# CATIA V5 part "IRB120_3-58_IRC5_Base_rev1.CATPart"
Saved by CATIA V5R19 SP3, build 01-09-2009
Part number: Link0
Revision: ANY
Definition: UNKNOWN
Nomenclature: Link0
Source: Unknown
Bounding box of the stored display mesh (mm): x -211.2 to 90, y -90.262 to 90.262, z 0 to 166.334
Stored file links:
  Z:\Projects\ABB_Robotics\ABB LIB\V5\V5PARTS\ABB\120\IRB120_3-58_IRC5_Base_rev1.CATPart
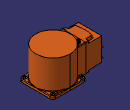
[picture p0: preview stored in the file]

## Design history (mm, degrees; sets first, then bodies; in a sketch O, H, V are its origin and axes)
Body1 "NONE" (main body)
  Solid1: solid without history
Body2 "NONE"
  Solid2: solid without history
Body3 "NONE"
  Solid3: solid without history
Body4 "NONE"
  Solid4: solid without history
Body5 "NONE"
  Solid5: solid without history
Body6 "NONE"
  Solid6: solid without history
Body7 "NONE"
  Solid7: solid without history
Body8 "NONE"
  Solid8: solid without history
Body9 "NONE"
  Solid9: solid without history
Body10 "NONE"
  Solid10: solid without history
Body11 "NONE"
  Solid11: solid without history
Body12 "NONE"
  Solid12: solid without history
Body13 "NONE"
  Solid13: solid without history
Body14 "NONE"
  Solid14: solid without history
Body15 "NONE"
  Solid15: solid without history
